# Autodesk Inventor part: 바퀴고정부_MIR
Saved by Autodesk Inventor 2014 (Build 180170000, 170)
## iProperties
Created: 2015-05
Part Number: 바퀴고정부_MIR
Material: 일반
Vendor: CBT Solutions
Document SubType Name: 모델링
Designer: Administrator
Appearance: 기본값
Company: 한국ATC센터
Author: KYOUNG IL JANG
Comments: 파생
d0: 1.000 ul
d0_1: 1.000 ul
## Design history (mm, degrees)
derived "바퀴고정부.ipt" dims count "d0" = 1
feature "솔리드1::바퀴고정부.ipt" dims count "d0" = 1
tag "피쳐 태그1"
node "솔리드1"
other parameters: "d0_1" = 1
